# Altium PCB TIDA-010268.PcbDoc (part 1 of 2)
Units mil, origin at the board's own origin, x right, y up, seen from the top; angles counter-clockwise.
Board outline 3937.2 x 2362.29 mil, 2 copper layers (Top Layer, Bottom Layer), stack 62 mil thick; 154 components, 100 nets, 480 pads, 602 vias.
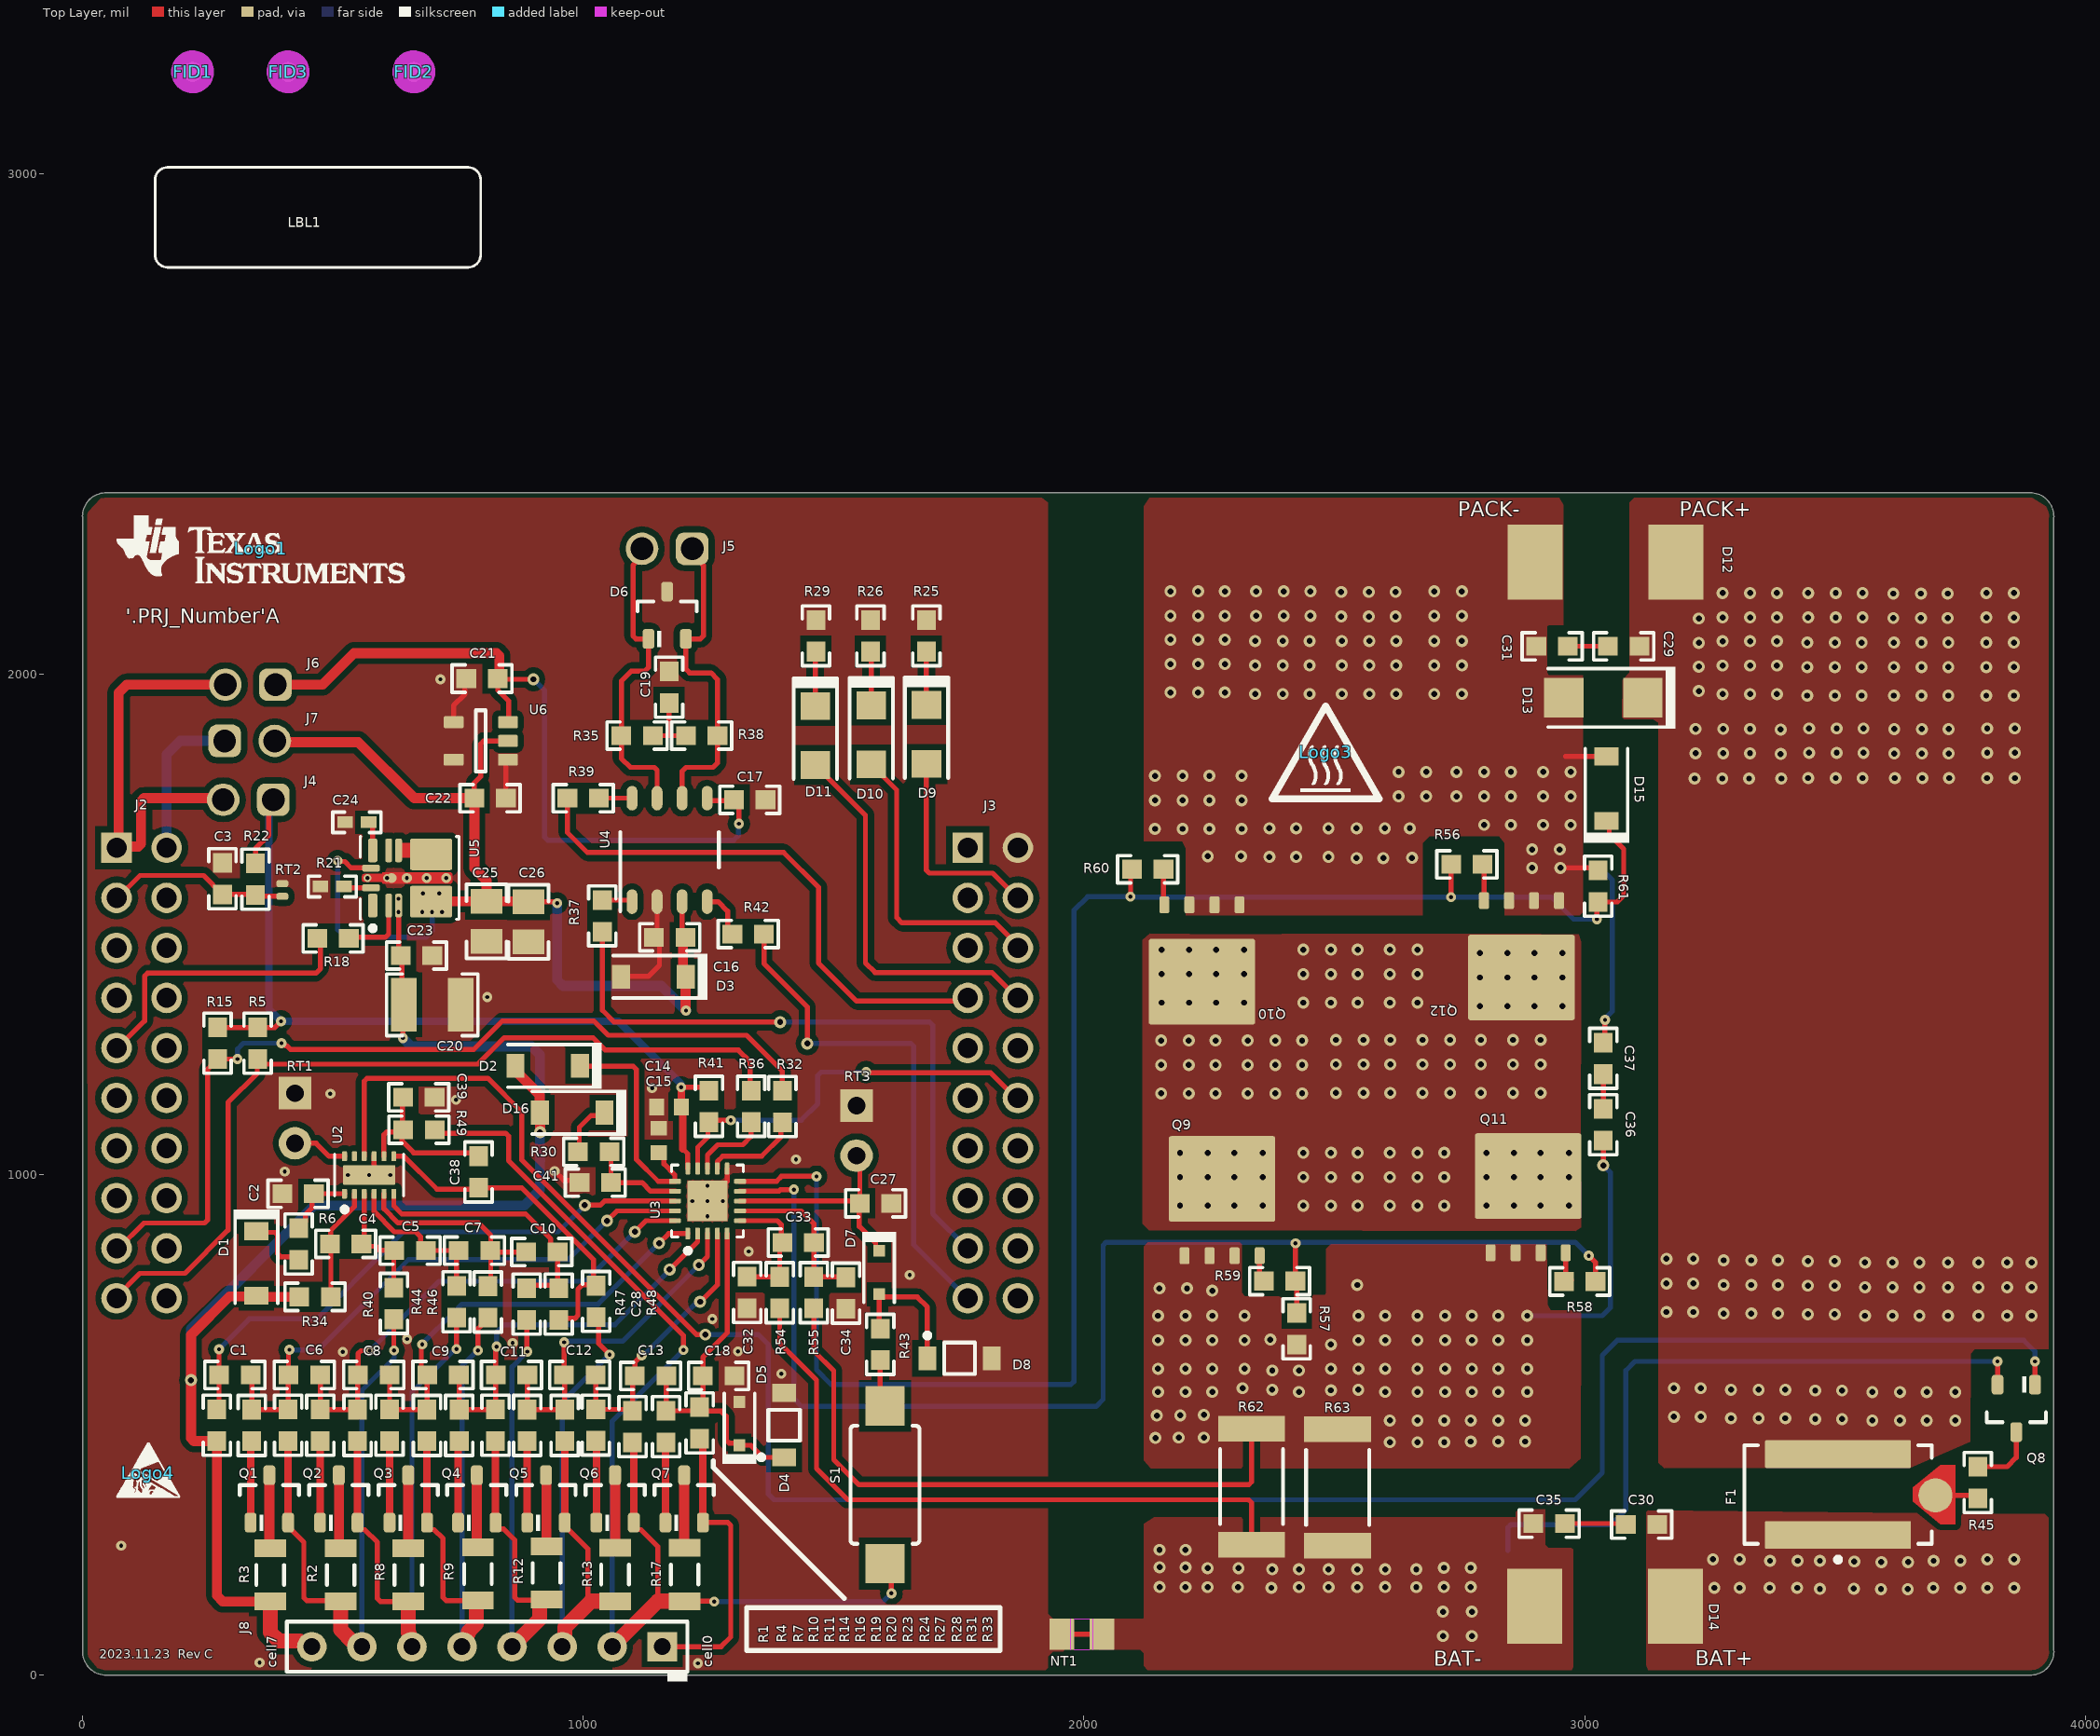
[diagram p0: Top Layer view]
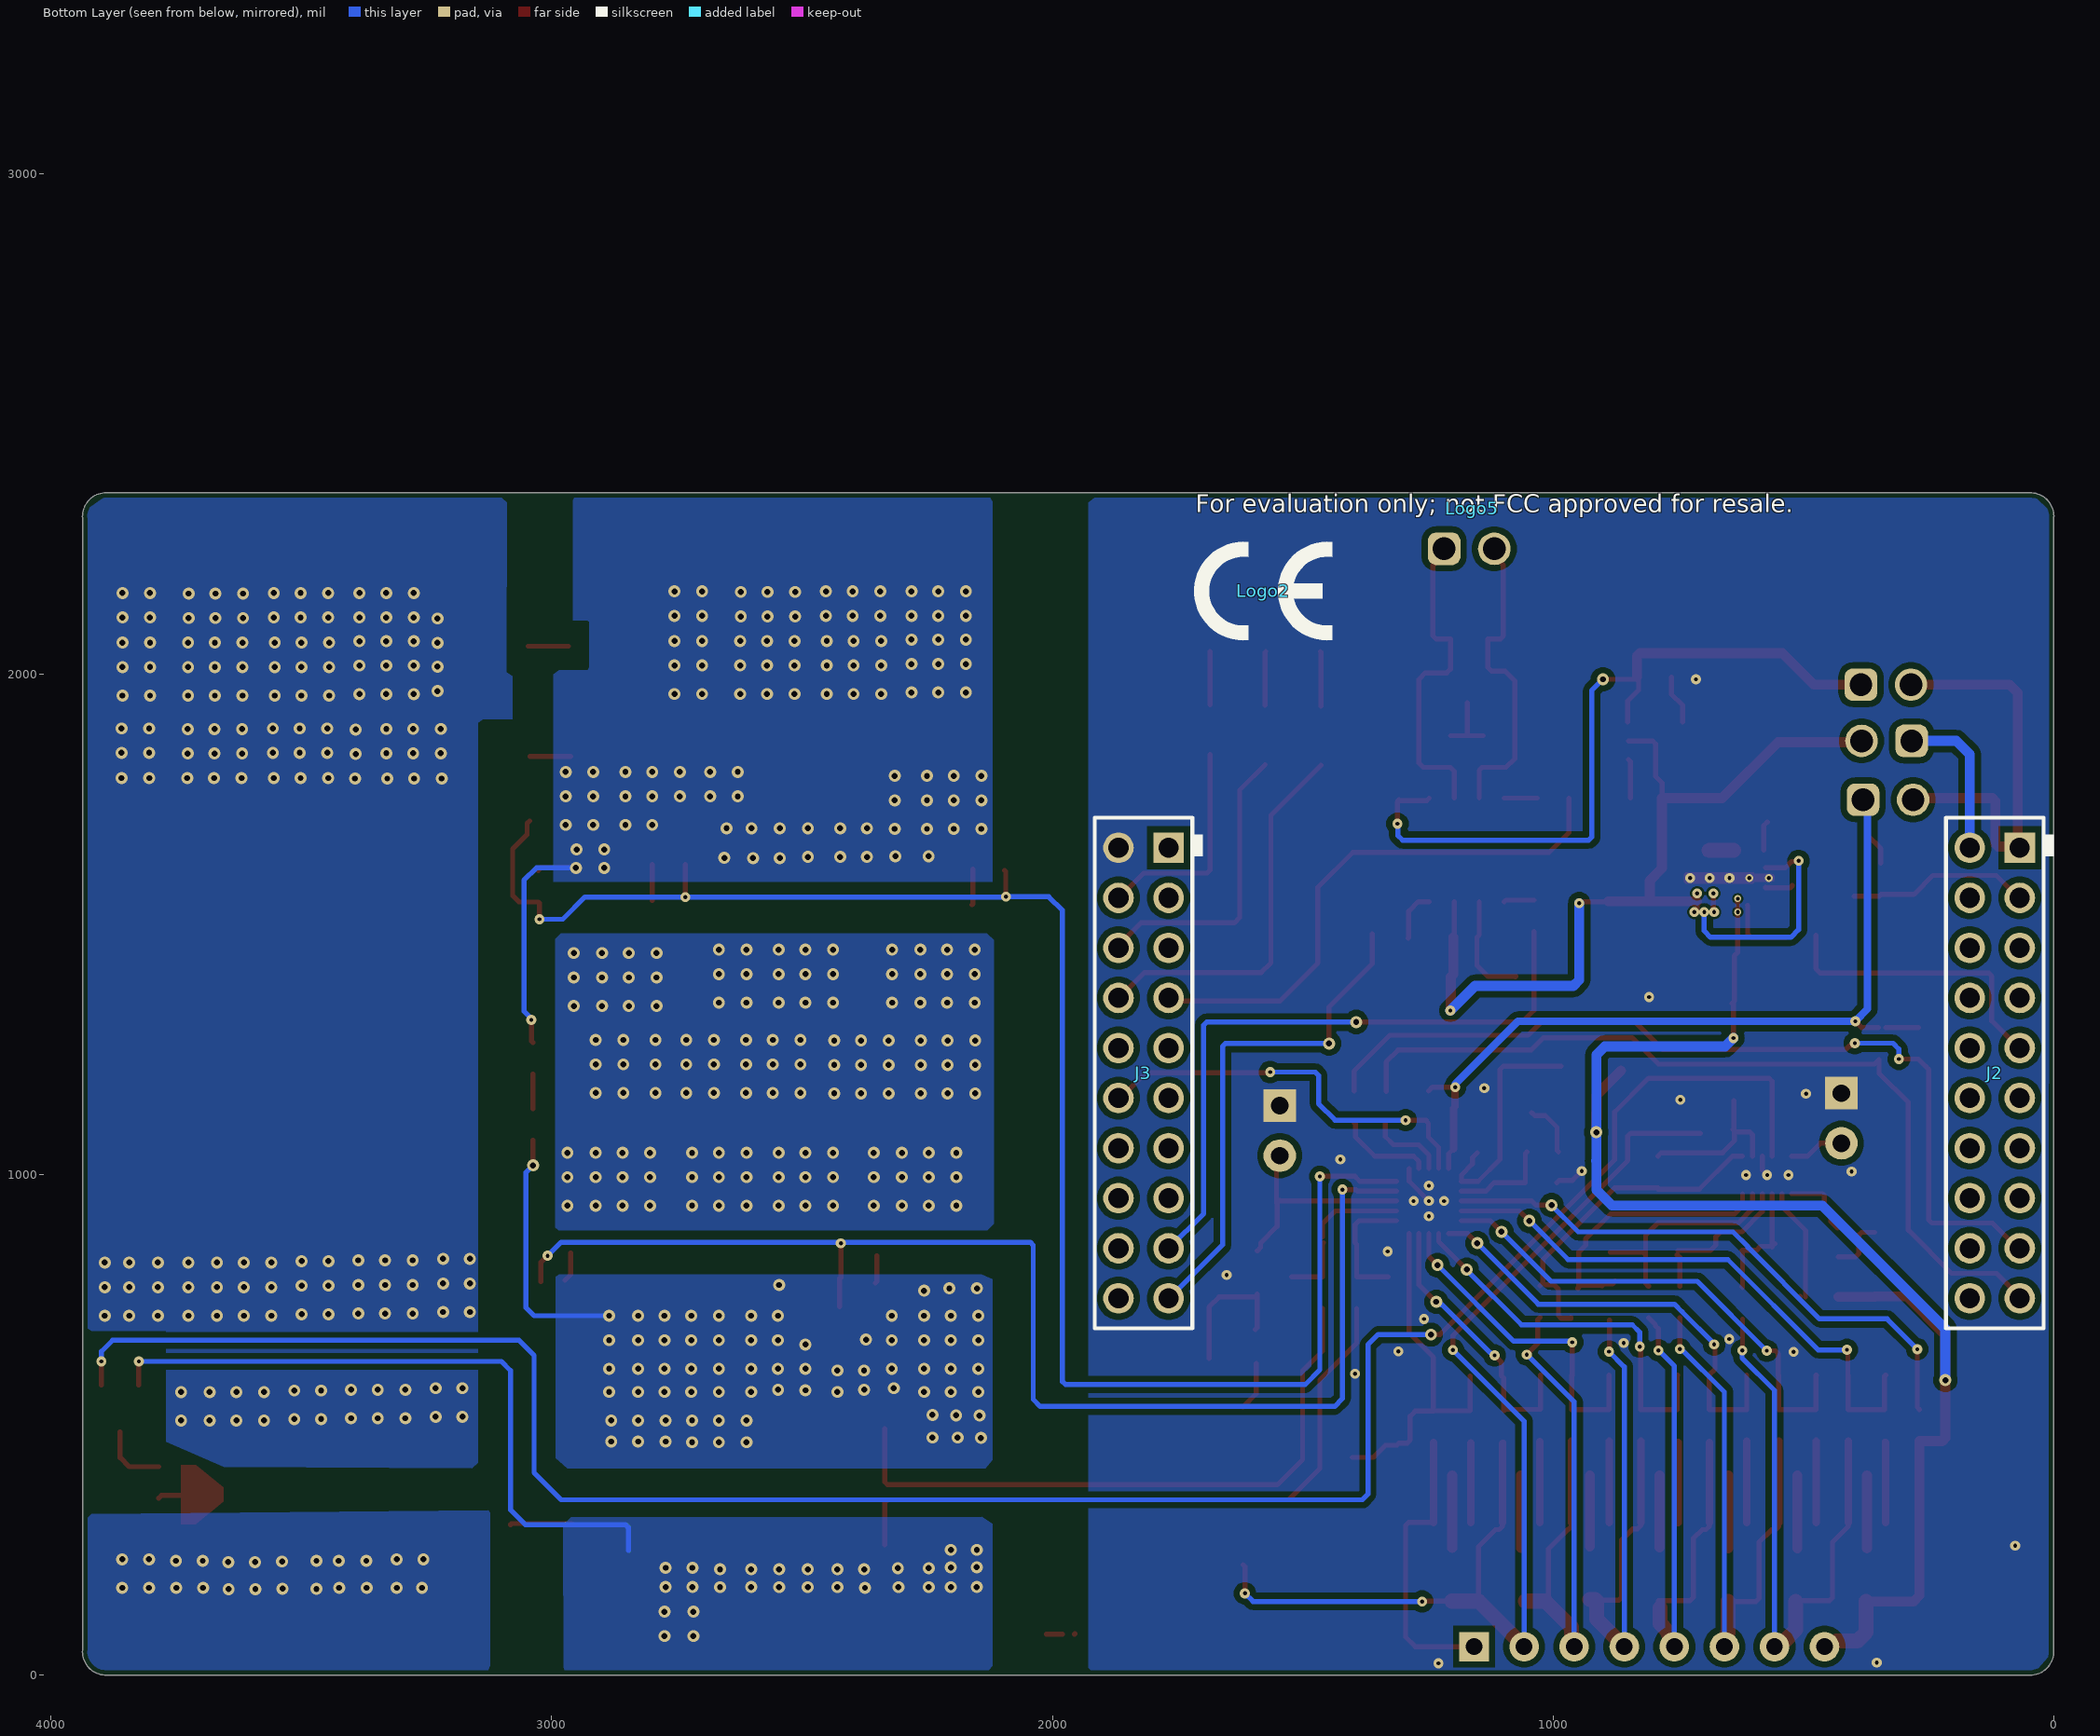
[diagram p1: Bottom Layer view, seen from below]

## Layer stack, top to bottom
Top Solder: solder mask 0.4, Solder Resist, Dk 3.5
Top Layer: signal copper 1.4
Dielectric1: core 59.2, FR-4 High Tg, Dk 4.8
Bottom Layer: signal copper 1.4
Bottom Solder: solder mask 0.4, Solder Resist, Dk 3.5

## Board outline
47.27,0.06 cw(c47.48,47.45) 0.09,47.99 0,2314.52 -0.09,2315.12 cw(c47.3,2314.91) 47.84,2362.29 47.69,2362.2 3887.56,2362.2 3889.92,2362.29 cw(c3889.71,2314.91) 3937.09,2314.37 3937.01,2312.76 3937.01,49.03 3937.11,47.19 cw(c3889.73,47.39) 3889.19,0.01 3887.97,0

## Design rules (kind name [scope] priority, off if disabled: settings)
AcuteAngle [InNet('5V')] p1: minimum=1.00000000000000E+0001 checktracksonly=FALSE
AcuteAngle AcuteAngle_ALL [All] p2: minimum=4.50000000000000E+0001 checktracksonly=FALSE
AssemblyTestPointUsage [All] p1: valid=2
BoardOutlineClearance BoardOutlineClearance_MountingHoles [OnCopper and InComponentClass('Mounting Holes')] p1: gap=10 ignorepadtopadclearanceinfootprint=FALSE
BoardOutlineClearance BoardOutlineClearance_Poly [OnCopper and IsPoly] p2: gap=10 ignorepadtopadclearanceinfootprint=FALSE
BoardOutlineClearance [OnCopper and Not InComponentClass('Logo') and not InComponentClass('FiducialMark') and not InRegion(1000,500,4000,800) and not InPoly] p3: gap=10 ignorepadtopadclearanceinfootprint=FALSE
Clearance [Not  (InNamedPolygon('Top Layer-GND')) vs InComponent('U5')] p1: gap=4 ignorepadtopadclearanceinfootprint=TRUE
Clearance Clearance_Keepouts [((IsTrack Or IsArc) And Not InPoly) And IsFree and IsKeepOut vs ((IsTrack Or IsArc) And Not InPoly) And IsFree and IsKeepOut] p2: gap=0 ignorepadtopadclearanceinfootprint=FALSE
Clearance Clearance_Poly [InPolygon] p3: gap=12 ignorepadtopadclearanceinfootprint=TRUE
Clearance Clearance_FiducialMark [IsKeepOut and InComponentClass('FiducialMark') vs IsPad and InComponentClass('FiducialMark')] p4: gap=0 ignorepadtopadclearanceinfootprint=FALSE
Clearance Clearance_All [All] p5: gap=7.87 ignorepadtopadclearanceinfootprint=TRUE
ComponentClearance ComponentClearance_MountingHoles_FiducialMarks [InComponentClass('Mounting Holes') vs InComponentClass('FiducialMark')] p1: gap=50 collisioncheckmode=3 verticalgap=10 showdistances=FALSE
ComponentClearance ComponentClearance_Shunt [InComponentClass('Header') vs InComponentClass('Shunt')] p2: gap=0 collisioncheckmode=3 verticalgap=0 showdistances=FALSE
ComponentClearance ComponentClearance_Logo [InComponentClass('Logo')] p3: gap=30 collisioncheckmode=3 verticalgap=10 showdistances=FALSE
ComponentClearance ComponentClearance_ScrewToNut [(HasFootprint('NY PMS 440 0025 PH')) vs (HasFootprint('Keystone_1902C'))] p4: gap=5 collisioncheckmode=3 verticalgap=10 showdistances=FALSE
ComponentClearance ComponentClearance_MountingHoles [InComponentClass('Mounting Holes')] p5: gap=100 collisioncheckmode=3 verticalgap=100000 showdistances=FALSE
ComponentClearance ComponentClearance_SmallPassives [HasFootprint('0201*') or HasFootprint('0402*') or HasFootprint('0508') or HasFootprint('0603*') or HasFootprint('0612') or HasFootprint('0805*') or HasFootprint('0815*') or HasFootprint('0830*') or HasFootprint('1206*') or HasFootprint('1210*') or HasFootprint('1808*') or HasFootprint('1812*') or HasFootprint('1825*') or HasFootprint('2010*') or HasFootprint('2220*') or HasFootprint('2225*') or HasFootprint('2512*') or HasFootprint('2728*') or HasFootprint('3518*') vs HasFootprint('0201*') or HasFootprint('0402*') or HasFootprint('0508') or HasFootprint('0603*') or HasFootprint('0612') or HasFootprint('0805*') or HasFootprint('0815*') or HasFootprint('0830*') or HasFootprint('1206*') or HasFootprint('1210*') or HasFootprint('1808*') or HasFootprint('1812*') or HasFootprint('1825*') or HasFootprint('2010*') or HasFootprint('2220*') or HasFootprint('2225*') or HasFootprint('2512*') or HasFootprint('2728*') or HasFootprint('3518*')] p6: gap=14.96 collisioncheckmode=3 verticalgap=10 showdistances=FALSE
ComponentClearance ComponentClearance_THtoSMT [IsThruComponent vs IsSMTComponent] p7: gap=25 collisioncheckmode=3 verticalgap=25 showdistances=FALSE
ComponentClearance ComponentClearance_THtoTH [IsThruComponent vs IsThruComponent] p8: gap=10 collisioncheckmode=3 verticalgap=30 showdistances=FALSE
ComponentClearance [All] p9: gap=10 collisioncheckmode=3 verticalgap=10 showdistances=FALSE
DiffPairsRouting [All] p1: maxlimit=100 minlimit=10 mostfreqgap=10 toplayer_minwidth=15 toplayer_maxwidth=15 toplayer_prefwidth=15 bottomlayer_minwidth=15 bottomlayer_maxwidth=15 bottomlayer_prefwidth=15 maxuncoupledlength=1000
FabricationTestPointUsage TestPointUsage [All] p1: valid=2 allowmultiple=FALSE
FabricationTestpoint Testpoint [All] p1: side=3 testpointundercomponent=TRUE minsize=40 maxsize=100 preferedsize=60 minholesize=0 maxholesize=40 preferedholesize=32 testpointgrid=1 allowsidetop=TRUE allowsidebottom=TRUE usegrid=TRUE gridtolerance=0.01
FanoutControl Fanout_LCC [IsLCC] p1: bgadir=Out bgaviamode=Centered fanoutstyle=Auto fanoutdirection=Alternating viagrid=1 // Fanout_LCC (Default Rule)
FanoutControl Fanout_BGA [IsBGA] p2: bgadir=Out bgaviamode=Centered fanoutstyle=Auto fanoutdirection=Alternating viagrid=1 // Fanout_BGA (Default Rule)
FanoutControl Fanout_Default [All] p4: bgadir=Out bgaviamode=Centered fanoutstyle=Auto fanoutdirection=Alternating viagrid=1 // Fanout_Default (Default Rule)
FanoutControl Fanout_Small [(CompPinCount < 5)] p5: bgadir=Out bgaviamode=Centered fanoutstyle=Auto fanoutdirection=OutThenIn viagrid=1 // Fanout_Small (Default Rule)
HoleSize [All] p1: absolutevalues=TRUE maxlimit=251 minlimit=7.87 maxpercent=80.000 minpercent=20.000
MinimumAnnularRing MinimumAnnularRing_ThermalPadVias [IsVia and InAnyComponent] p1: minimumring=2
MinimumAnnularRing [All] p2: minimumring=2
MinimumSolderMaskSliver MinimumSolderMaskSliver_Logo [InComponentClass('Logo') vs InComponentClass('Logo')] p1: minsoldermaskwidth=0.7
MinimumSolderMaskSliver [All] p2: minsoldermaskwidth=3.94
PlaneConnect [All] p1: planeconnectstyle=Relief reliefexpansion=10 reliefentries=4 reliefconductorwidth=10 reliefairgap=10
PolygonConnect [All] p1: connectstyle=Direct reliefconductorwidth=10 reliefentries=4 polygonreliefangle="90 Angle" airgapwidth=10
RoutingVias ThermalPadVias [IsVia and InAnyComponent] p1: holewidth=5 width=19.68 viastyle="Through Hole" minholewidth=5 minwidth=10 maxholewidth=12.99 maxwidth=25
RoutingVias [All] p2: holewidth=16 width=34 viastyle="Through Hole" minholewidth=5 minwidth=18 maxholewidth=40 maxwidth=65
SilkToBoardRegionClearance [Not ((IsComment or IsDesignator) And (Hide <> 'False')) and not InRegion(1000,500,4000,800)] p1:
SilkToSilkClearance SilkToSilkClearance_Pb-FreeLogo [(HasFootprint('Pb-Free_Overlay_Medium') OR HasFootprint('Pb-Free_Overlay_Small')) vs (HasFootprint('Pb-Free_Overlay_Medium') OR HasFootprint('Pb-Free_Overlay_Small'))] p1: silktosilkclearance=0
SilkToSilkClearance [All] p2: silktosilkclearance=3.94
SilkToSolderMaskClearance SilkToComponentPadClearance [(IsPad or IsFill or IsRegion) and InAnycomponent] p1: minsilkscreentomaskgap=3 clearancetoexposedcopper=TRUE
SilkToSolderMaskClearance "Silk to Solder Mask Opening" [All] p2: minsilkscreentomaskgap=3.94 clearancetoexposedcopper=FALSE
SolderMaskExpansion [All] p1: expansion=1.97 istentingtop=FALSE
UnRoutedNet [All] p1: checkbadconnections=TRUE
Width [InNet('5V')] p1: maxlimit=50 minlimit=1 preferedwidth=1
Width Width_all [All] p2: maxlimit=100 minlimit=6 preferedwidth=10 checkconnectedcopper=TRUE
14 further rules are at their usual default settings.

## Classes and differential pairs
component class "TIDA-010268_Power Rail": C29 C30 C31 C32 C33 C34 C35 C36 C37 D12 D13 D14 D15 F1 NT1 Q8 Q9 Q10 Q11 Q12 R45 R54 R55 R56 R57 R58 R59 R60 R61 R62 R63
component class "TIDA-010268_Monitor and CB": C1 C2 C3 C4 C5 C6 C7 C8 C9 C10 C11 C12 C13 C14 C15 C16 C17 C18 C19 C20 C21 C22 C23 C24 C25 C26 C27 C28 C38 C39 C41 D1 D2 D3 D4 D5 D6 D7 D8 D9 D10 D11 D16 J2 J3 J4 J5 J6 J7 J8 Q1 Q2 Q3 Q4 Q5 Q6 Q7 R1 R2 R3 R4 R5 R6 R7 R8 R9 R10 R11 R12 R13 R14 R15 R16 R17 R18 R19 R20 R21 R22 R23 R24 R25 R26 R27 R28 R29 R30 R31 R32 R33 R34 R35 R36 R37 R38 R39 R40 R41 R42 R43 R44 R46 R47 R48 R49 RT1 RT2 RT3 S1 U2 U3 U4 U5 U6
component class Header: J4 J5 J6 J7 J8
component class Logo: Logo1
component class TIDA-010268_Hardware: FID1 FID2 FID3 LBL1 Logo1 Logo2 Logo3 Logo4 Logo5
component class FiducialMark: FID1 FID2 FID3
component class Label: LBL1

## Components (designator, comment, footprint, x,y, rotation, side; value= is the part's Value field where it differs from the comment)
C1 "GRM188R71H224KAC4D" 0603 304.27,599.57 r0 top value=0.22uF
C2 "GRM188R72A104KA35J" 0603 430.47,961.86 r0 top value=0.1uF
C3 "GRM188R71H471KA01D" 0603 279.6,1591.23 r90 top value=470pF
C4 "GRM188R72A104KA35J" 0603 525.65,861.74 r0 top value=0.1uF
C5 "GRM188R72A104KA35J" 0603 654.43,848.32 r0 top value=0.1uF
C6 "GRM188R71H224KAC4D" 0603 442.95,599.57 r0 top value=0.22uF
C7 "GRM188R72A104KA35J" 0603 782.67,848.32 r0 top value=0.1uF
C8 "GRM188R71H224KAC4D" 0603 581.74,599.57 r0 top value=0.22uF
C9 "GRM188R71H224KAC4D" 0603 720.04,599.57 r0 top value=0.22uF
C10 "GRM188R72A104KA35J" 0603 917.24,845.41 r0 top value=0.1uF
C11 "GRM188R71H224KAC4D" 0603 856.78,599.57 r0 top value=0.22uF
C12 "GRM188R71H224KAC4D" 0603 993.23,599.57 r0 top value=0.22uF
C13 "GRM188R71H224KAC4D" 0603 1134.68,597.75 r0 top value=0.22uF
C14 "GRM188R61E105KA12D" CAPC1608X90X35LL10T15 1171.52,1135.5 r0 top value=1uF
C15 "GRM188R61E105KA12D" CAPC1608X90X35LL10T15 1150.82,1068.27 r90 top value=1uF
C16 "GRM188R72A104KA35J" 0603 1172.86,1474.25 r0 top value=0.1uF
C17 "GRM188R72A104KA35J" 0603 1332.54,1748.9 r180 top value=0.1uF
C18 "GRM188R71H224KAC4D" 0603 1270.57,597.75 r0 top value=0.22uF
C19 "GRM188R72A104KA35J" 0603 1171.52,1973.78 r90 top value=0.1uF
C20 "GRM32CR72A105KA35L" 1210_180 698.45,1339.32 r0 top value=1uF
C21 "GRM188C71E225KE11D" 0603 797.88,1990.96 r180 top value=2.2uF
C22 "GRM188C71E225KE11D" 0603 814.05,1752.08 r0 top value=2.2uF
C23 "GRM188R72A104KA35J" 0603 667.11,1437.56 r0 top value=0.1uF
C24 "GRM155R6YA105KE11D" 0402 548,1704 r180 top value=1uF
C25 "GRM21BC81C226ME44L" 0805_HV 807.06,1506.08 r270 top value=22uF
C26 "GRM21BC81C226ME44L" 0805_HV 890.87,1505.07 r270 top value=22uF
C27 "GRM188R71H471KA01D" 0603 1583.89,942.47 r0 top value=470pF
C28 "GRM188R72A104KA35J" 0603 950.88,741.26 r270 top value=0.1uF
C29 "GRM188R72A104KA35J" 0603 3078,2055.52 r180 top value=0.1uF
C30 "GRM188R72A104KA35J" 0603 3113.74,300.87 r180 top value=0.1uF
C31 "GRM188R72A104KA35J" 0603 2935.05,2055.52 r180 top value=0.1uF
C32 "GRM188R72A104KA35J" 0603 1327.44,764.67 r90 top value=0.1uF
C33 "GRM188R72A104KA35J" 0603 1429.42,864.29 r0 top value=0.1uF
C34 "GRM188R72A104KA35J" 0603 1524.69,763.37 r270 top value=0.1uF
C35 "GRM188R72A104KA35J" 0603 2929,303 r180 top value=0.1uF
C36 "GRM188R72A104KA35J" 0603 3037.34,1099.87 r90 top value=0.1uF
C37 "GRM188R72A104KA35J" 0603 3037.34,1232.19 r90 top value=0.1uF
C38 "GRM188R72A104KA35J" 0603 790.97,1005.3 r90 top value=0.1uF
C39 "GRM188R72A104KA35J" 0603 671.59,1154.42 r0 top value=0.1uF
C41 "GRM188R72A104KA35J" 0603 1024.06,983.98 r0 top value=0.1uF
D1 "1N6263W-7-F" SOD-123 347.23,822.68 r270 top value=60V
D2 "1N6263W-7-F" SOD-123 929.06,1217.36 r180 top value=60V
D3 "MMSZ4690T1G" SOD-123 1140.11,1395.22 r180 top value=5.6V
D4 "MMSZ4685T1G" ONSC-SOD-123-2-425-04_V 1401.18,499.63 r90 top
D5 "BAT42WS-7-F" SOD-323 1312.15,502.79 r90 top value=30V
D6 "NUP2105L" SOT-23 1167.67,2117.55 r90 top value=24V
D7 "PMEG1030EJ,115" SOD-323F 1591.04,804.48 r270 top value=10V
D8 "MMSZ4678T1G" ONSC-SOD-123-2-425-04_V 1751.59,633.07 r0 top
D9 "150120RS75000" WL_SMCW_RED_1206 1685.38,1879.29 r270 top value=Red
D10 "150120RS75000" WL_SMCW_RED_1206 1575.11,1878.36 r270 top value=Red
D11 "150120RS75000" WL_SMCW_RED_1206 1463.38,1877.29 r270 top value=Red
D12 "SMCJ30CA" SMC_Bi 3041.87,2223.52 r0 top value=30V
D13 "MURA110T3G" SMA 3037.34,1952.56 r180 top value=100V
D14 "SMCJ30CA" SMC_Bi 3041,138 r0 top value=30V
D15 "MMSZ5246B-7-F" SOD-123 3043.55,1771.02 r90 top value=16V
D16 "1N6263W-7-F" SOD-123 978.07,1123.72 r180 top value=60V
F1 "SFK-3045" "FP-SFK-3045_FUSE, SMT-MFG" 3506,361 r180 top
FID1 "Fiducial" Fiducial10-20 220.02,3203.15 r0 top
FID2 "Fiducial" Fiducial10-20 661.63,3203.15 r0 top
FID3 "Fiducial" Fiducial10-20 410.62,3203.15 r0 top
J2 "SSQ-110-03-T-D" Samtec_SSQ-110-03-x-D 118,1203 r270 bottom
J3 "SSQ-110-03-T-D" Samtec_SSQ-110-03-x-D 1818,1203 r270 bottom
J4 "61300211121" WURTH_61300211121 331.01,1748.9 r180 top
J5 "61300211121" WURTH_61300211121 1167.58,2250.31 r180 top
J6 "61300211121" WURTH_61300211121 335.26,1978.81 r180 top
J7 "61300211121" WURTH_61300211121 334.01,1866.5 r0 top
J8 "800-10-008-10-001000" Mill-Max_800-10-008-10-001000 807.97,57.03 r180 top
LBL1 "THT-14-423-10" Label_650x200 470.01,2912.4 r0 top
Logo1 "Texas Instruments" TI_Stacked_Overlay_Small_Vertical 355.76,2250.31 r270 top
Logo2 "CE Mark" CE_Mark_5mm 1578.95,2165.68 r180 bottom
Logo3 "CAUTION HOT SURFACE" IEC_HotSurface_small 2482.48,1843.7 r0 top (schematic designator LOGO3)
Logo4 "ESD Susceptible" ESD_Overlay_Small 130.47,403.8 r0 top
Logo5 "FCC disclaimer" FCC_disclaimer 1161.67,2331 r180 bottom
NT1 "Net-Tie" Net-Tie_0805_HV_NoOverlay 1996.02,81.92 r0 top net-tie
Q1 "BSR14" SOT-23 373.16,352.25 r90 top value="40 V"
Q2 "BSR14" SOT-23 511.85,352.25 r90 top value="40 V"
Q3 "BSR14" SOT-23 650.64,352.25 r90 top value="40 V"
Q4 "BSR14" SOT-23 787.52,352.25 r90 top value="40 V"
Q5 "BSR14" SOT-23 925.68,352.25 r90 top value="40 V"
Q6 "BSR14" SOT-23 1063.68,352.25 r90 top value="40 V"
Q7 "BSR14" SOT-23 1201.68,352.25 r90 top value="40 V"
Q8 "IRLML2060TRPBF" SOT-23 3862,533 r270 top value=60V
Q9 "CSD18540Q5B" DNK0008A 2275.82,949 r90 top value=60V
Q10 "CSD18540Q5B" DNK0008A 2235.64,1427.95 r270 top value=60V
Q11 "CSD18540Q5B" DNK0008A 2887.13,954.69 r90 top value=60V
Q12 "CSD18540Q5B" DNK0008A 2873.8,1436.38 r270 top value=60V
R1 "CRCW0603100RFKEA" 0603 268.31,499.25 r90 top value=100
R2 "CRCW120680R6FKEA" RESC3216X60X45LL10T20 515.68,200.45 r90 top
R3 "CRCW120680R6FKEA" RESC3216X60X45LL10T20 374.87,200.45 r90 top
R4 "CRCW0603300RJNEA" 0603 337.97,499.02 r90 top value=300
R5 "CRCW060310K0FKEA" 0603 349.86,1262.56 r90 top value=10.0k
R6 "CRCW0603300RJNEA" 0603 431.84,861.55 r90 top value=300
R7 "CRCW0603100RFKEA" 0603 410.57,499.25 r90 top value=100
R8 "CRCW120680R6FKEA" RESC3216X60X45LL10T20 650.64,200.45 r90 top
R9 "CRCW120680R6FKEA" RESC3216X60X45LL10T20 789.6,202.36 r90 top
R10 "CRCW0603300RJNEA" 0603 474.86,499.25 r90 top value=300
R11 "CRCW0603100RFKEA" 0603 549.25,499.02 r90 top value=100
R12 "CRCW120680R6FKEA" RESC3216X60X45LL10T20 926.72,204.28 r90 top
R13 "CRCW120680R6FKEA" RESC3216X60X45LL10T20 1063.68,201.13 r90 top
R14 "CRCW0603300RJNEA" 0603 613.24,499.25 r90 top value=300
R15 "CRCW060310K0FKEA" 0603 269.82,1262.56 r90 top value=10.0k
R16 "CRCW0603100RFKEA" 0603 688.04,499.02 r90 top value=100
R17 "CRCW120680R6FKEA" RESC3216X60X45LL10T20 1202.57,201.13 r90 top
R18 "CRCW06031K00FKEA" 0603 500.51,1471.78 r0 top value=1.00k
R19 "CRCW0603300RJNEA" 0603 752.46,499.02 r90 top value=300
R20 "CRCW0603100RFKEA" 0603 824.92,499.25 r90 top value=100
R21 "CRCW040241K2FKED" 0402 498.79,1575.6 r0 top value=41.2k
R22 "CRCW060310K0FKEA" 0603 345.55,1590.37 r90 top value=10.0k
R23 "CRCW0603300RJNEA" 0603 888.28,499.02 r90 top value=300
R24 "CRCW0603100RFKEA" 0603 963.08,499.02 r90 top value=100
R25 "CRCW0603470RJNEA" 0603 1685.38,2076.29 r270 top value=470
R26 "CRCW0603470RJNEA" 0603 1573.77,2076.29 r270 top value=470
R27 "CRCW0603300RJNEA" 0603 1025.15,499.63 r90 top value=300
R28 "CRCW0603100RFKEA" 0603 1098.57,496.74 r90 top value=100
R29 "CRCW0603470RJNEA" 0603 1464.88,2076.29 r270 top value=470
R30 "CRCW0603300RJNEA" 0603 1020.85,1045.5 r0 top value=300
R31 "CRCW0603300RJNEA" 0603 1165.62,496.74 r90 top value=300
R32 "CRCW0603100RJNEA" 0603 1397.69,1135.9 r90 top value=100
R33 "CRCW0603100RFKEA" 0603 1232.59,504.17 r90 top value=100
R34 "CRCW06031K00FKEA" 0603 464.47,755.77 r0 top value=1.00k
R35 "CRCW060360R4FKEA" 0603 1107.69,1877.02 r180 top value=60.4
R36 "CRCW0603100RJNEA" 0603 1335.46,1136.36 r90 top value=100
R37 "CRCW0603100RJNEA" 0603 1038.18,1516.88 r90 top value=100
R38 "CRCW060360R4FKEA" 0603 1236.51,1877.02 r180 top value=60.4
R39 "CRCW0603100RJNEA" 0603 1000.05,1752.08 r0 top value=100
R40 "CRCW06031K00FKEA" 0603 621.79,742.68 r90 top value=1.00k
R41 "CRCW060310K0FKEA" 0603 1251.25,1136.36 r270 top value=10.0k
R42 "CRCW0603100RJNEA" 0603 1329.41,1480.78 r180 top value=100
R43 "CRCW060310K0FKEA" 0603 1593.1,660.87 r90 top value=10.0k
R44 "CRCW06031K00FKEA" 0603 747.13,745.88 r90 top value=1.00k
R45 "CRCW0603300RJNEA" 0603 3785,385 r270 top value=300
R46 "CRCW06031K00FKEA" 0603 809.5,745.63 r90 top value=1.00k
R47 "CRCW06031K00FKEA" 0603 887.25,741.26 r90 top value=1.00k
R48 "CRCW06031K00FKEA" 0603 1025.83,746.78 r90 top value=1.00k
R49 "CRCW06031K00FKEA" 0603 672.11,1089.83 r180 top value=1.00k
R54 "CRCW0603100RFKEA" 0603 1392.46,764.3 r90 top value=100
R55 "CRCW0603100RFKEA" 0603 1460.46,764.3 r270 top value=100
R56 "CRCW0603330RJNEA" 0603 2764.76,1619.77 r180 top value=330
R57 "CRCW060310M0JNEA" 0603 2424.99,692.09 r90 top value=10Meg
R58 "CRCW0603330RJNEA" 0603 2990.25,786.51 r0 top value=330
R59 "CRCW0603330RJNEA" 0603 2390.88,787.39 r0 top value=330
R60 "CRCW0603330RJNEA" 0603 2127.23,1610.22 r180 top value=330
R61 "CRCW060310M0JNEA" 0603 3026.82,1576.22 r270 top value=10Meg
R62 "CSNL2512FT2L00" 2512 2334.73,376.73 r90 top value=0.002
R63 "CSNL2512FT2L00" 2512 2506.54,375.14 r90 top value=0.002
RT1 "103AT-2" THERMISTOR_103AT-2 424.25,1112.67 r270 top value=10k
RT2 "TMP6131DECR" DEC0002A 399.19,1568.71 r270 top
RT3 "103AT-2" THERMISTOR_103AT-2 1545.86,1087.95 r270 top value=10k
S1 "RS-032G05A3-SM RT" SW_RS-032G05A3-SM 1602.59,380.47 r270 top
U2 "BQ7720700DSSR" DSS0012B-MFG 572.51,999.26 r90 top
U3 "BQ76907RGR" RGR0020A-MFG 1248.18,947.26 r90 top
U4 "TCAN1042HGVDQ1" D0008A_L 1172.54,1648.74 r90 top
U5 "TPSM365R6V5RDNR" RDN0011A-MFG 656.82,1592.63 r90 top
U6 "TLV70433DBVT" DBV0005A_N 795.35,1866.5 r180 top

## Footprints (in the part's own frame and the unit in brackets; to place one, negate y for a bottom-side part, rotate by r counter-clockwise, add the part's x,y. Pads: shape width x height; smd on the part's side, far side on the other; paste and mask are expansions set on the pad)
0402 [mm] "0402 from SM-752 data"
  rect 0.8x0.6 smd: 1(-0.6,0) 2(0.6,0)
  silkscreen extent -1.22,-0.52 1.22,0.52, body extent -0.55,-0.3 0.55,0.3, height 0.6
0603 [mm] "0603 from SM-752 data"
  rect 1x0.95 smd: 1(-0.8,0) 2(0.8,0)
  silkscreen extent -1.52,-0.69 1.52,0.69, body extent -0.87,-0.47 0.87,0.47, height 1
0805_HV [mil] "0805 with 30mil clearance between pads"
  rect 50x63 smd: 1(-40,0) 2(40,0)
  silkscreen extent -74,-40 74,40, body extent -43,-29 43,29, height 57
1210_180 [mm] "1210"
  rect 1.3x2.7 smd: 1(-1.45,0) 2(1.45,0)
  silkscreen extent -2.32,-1.57 2.32,1.57, body extent -1.7,-1.35 1.7,1.35, height 1.8
2512 [mm] "Chip Resistor, Body 6.3x3.2mm, IPC Medium Density"
  rect 1.3x3.4 smd: 1(-2.95,0) 2(2.95,0)
  silkscreen extent -1.9,-1.6 1.9,1.6, body extent -3.22,-1.67 3.22,1.67, height 0.71
CAPC1608X90X35LL10T15 [mm] "Chip Capacitor, 2-Leads, Body 1.60x0.80mm, IPC High Density"
  rect 0.75x0.85 smd: 1(-0.625,0) 2(0.625,0)
  body extent -0.85,-0.45 0.85,0.45, height 0.9
CE_Mark_5mm [mil] "Minimum text height for CE Mark"
  silkscreen extent -138,-98 138,98
D0008A_L [mm] "SOIC, 8-Leads, Body 4.9x3.9mm, Pitch 1.27mm, IPC High Density"
  oval 1.25x0.55 smd: 1(-2.625,1.905) 2(-2.625,0.635) 3(-2.625,-0.635) 4(-2.625,-1.905) 5(2.625,-1.905) 6(2.625,-0.635) 7(2.625,0.635) 8(2.625,1.905)
  silkscreen extent -3.1,-2.5 0.9,2.5, body extent -3,-2.45 3,2.45, height 1.63
DBV0005A_N [mm] "SOT23, 5-Leads, Body 2.9x1.6mm, Pitch 0.95mm, Lead Span 2.8mm, IPC Medium Density"
  rrect17% 1x0.6 smd: 1(-1.375,0.95) 2(-1.375,0) 3(-1.375,-0.95) 4(1.375,-0.95) 5(1.375,0.95)
  silkscreen extent -0.25,-1.55 0.25,1.55, body extent -1.42,-1.46 1.42,1.46, height 1.09
DEC0002A [mm] "X1SON-2"
  rrect57% 0.35x0.6 smd paste-0.5 mask-0.05: 1(-0.325,0) 2(0.325,0)
  rrect33% 0.3x0.5 on Top Paste: 1S(-0.35,0) 2S(0.35,0)
  body extent -0.5,-0.3 0.5,0.3, height 0.5
DNK0008A [mm] "SON, 8-Leads, Body 5x6mm"
  rrect39% 0.86x0.51 smd paste-0.05 mask-0.05: 1(-2.82,1.905) 2(-2.82,0.635) 3(-2.82,-0.635) 4(-2.82,-1.905) 5(2.82,-1.905) 6(2.82,-0.635) 7(2.82,0.635) 8(2.82,1.905)
  rrect40% 0.25x0.555 on Top Solder: 9(-0.83,2.372) 9(-0.83,-2.372)
  rrect40% 0.25x0.555 on Top Paste: 9(-0.83,2.372) 9(-0.83,-2.372)
  rrect11% 0.95x1.13 on Top Paste: 9(-0.535,1.33) 9(-0.535,0) 9(-0.535,-1.33) 9(0.615,1.33) 9(0.615,0) 9(0.615,-1.33) 9(1.765,-1.33) 9(1.765,0) 9(1.765,1.33)
  rrect3% 3.58x4 on Top Solder: 9(0.75,0)
  rrect5% 4.34x5.4 smd paste-3 mask-3: 9(1.08,0)
  body extent -3.05,-2.55 3.05,2.55, height 1.06
DSS0012B-MFG [mm]
  rrect40% 0.5x0.25 smd paste+0 mask+0: 1(-0.95,1.25) 2(-0.95,0.75) 3(-0.95,0.25) 4(-0.95,-0.25) 5(-0.95,-0.75) 6(-0.95,-1.25) 7(0.95,-1.25) 8(0.95,-0.75) 9(0.95,-0.25) 10(0.95,0.25) 11(0.95,0.75) 12(0.95,1.25)
  rrect10% 1x2.65 smd paste-1000 mask+0: 13(0,0)
  silkscreen extent -1.87,-1.75 1.05,1.75, body extent -1.3,-1.65 1.3,1.65, height 0.25
ESD_Overlay_Small [mil]
  silkscreen extent -62,-48 64,61
FCC_disclaimer [mil]
Fiducial10-20 [mm]
  round 1 smd mask+0.5: 1(0,0)
  Top Layer keep-out circle w1.178: c0,0 r0.5
"FP-SFK-3045_FUSE, SMT-MFG" [mm]
  rrect7% 7.4x1.4 smd paste+0 mask+0: T1(0,2.05) T3(0,-2.05)
  round 1.729 smd paste+0 mask+0: T2(-4.942,0.045)
  Top Layer region: -3.8,-0.35 -3.8,0.35 -5.2,1.5 -5.95,1.5 -5.95,-1.5 -5.2,-1.5
  silkscreen extent -4.75,-2.5 4.75,3.42, body extent -6.05,-2.85 4.85,2.85, height 0.25
IEC_HotSurface_small [mil]
  silkscreen extent -107,-93 107,92
Label_650x200 [mil] "Thermal Transfer Label"
  round 1 on Mech13: 0(0,0)
  silkscreen extent -325,-100 325,100, body extent -325,-100 325,100, height 1
Mill-Max_800-10-008-10-001000 [mm] "Mill-Max"
  rect 1.5x1.5 hole 0.85: 1(-8.89,0)
  round 1.5 hole 0.85: 2(-6.35,0) 3(-3.81,0) 4(-1.27,0) 5(1.27,0) 6(3.81,0) 7(6.35,0) 8(8.89,0)
  silkscreen extent -10.16,-1.27 10.16,1.78, body extent -10.16,-1.27 10.16,1.27, height 8.13
Net-Tie_0805_HV_NoOverlay [mil] "0805_HV pads tied by 10mil copper trace which can be cut.  An 0805 part can be placed on pads."
  rect 50x63 smd paste-25: 1(-40,0) 2(40,0)
  Top Layer lines w10: -16,0 16,0
  Top Layer keep-out lines w1: -22,-30.91 -22,30.91 ; -14.96,-30.91 14.96,-30.91 ; -14.96,30.91 14.96,30.91 ; 22,-30.91 22,30.91
ONSC-SOD-123-2-425-04_V [mm] "SOD, 2-Leads, Body 2.69x1.6mm"
  rect 0.91x1.22 smd: 1(-1.635,0) 2(1.635,0)
  silkscreen extent -1.76,-0.8 0.78,1.28, body extent -1.35,-0.8 1.35,0.8, height 1.35
RDN0011A-MFG [mm]
  rrect42% 1.2x0.475 smd paste-1000 mask-1000: 1(-1.4,1.962) 8(1.4,1.962)
  rrect57% 1.2x0.35 smd paste-1000 mask-1000: 2(-1.4,1.15) 3(-1.4,0.65) 6(1.4,0.65) 7(1.4,1.15)
  rrect13% 1.6x2.15 smd paste-1000 mask-1000: 4(-1.2,-1) 5(1.2,-1)
  rrect57% 0.35x0.9 smd paste-1000 mask-1000: 9(0.5,2.05) 11(-0.5,2.05)
  round 0.504 smd paste-1000 mask-1000: 10(0,1.005)
  Top Layer region: -0.2,2.4 -0.187,2.45 -0.15,2.487 -0.1,2.5 -0.1,2.5 0.1,2.5 0.15,2.487 0.187,2.45 0.2,2.4 0.2,2.4 0.2,1.515 0.203,1.5 0.212,1.487 0.225,1.478 0.24,1.475 0.24,1.475 0.24,1.475 0.26,1.47 0.275,1.455 0.28,1.435 0.28,1.435 0.28,-1.975 0.267,-2.025 0.23,-2.062 0.18,-2.075 0.18,-2.075 -0.18,-2.075 -0.23,-2.062 -0.267,-2.025 -0.28,-1.975 -0.28,-1.975 -0.28,1.435 -0.275,1.455 -0.26,1.47 -0.24,1.475 -0.24,1.475 -0.24,1.475 -0.225,1.478 -0.212,1.487 -0.203,1.5 -0.2,1.515 -0.2,1.515
  silkscreen extent -2.67,-2.42 2.1,2.6, body extent -2.1,-2.4 2.1,2.6, height 0.25
RESC3216X60X45LL10T20 [mm] "Chip Resistor, 2-Leads, Body 3.20x1.60mm, IPC High Density"
  rect 0.9x1.6 smd: 1(-1.35,0) 2(1.35,0)
  silkscreen extent -0.5,-0.7 0.5,0.7, body extent -1.65,-0.85 1.65,0.85, height 0.6
RGR0020A-MFG [mm]
  rrect42% 0.6x0.24 smd paste+0 mask+0: 1(-1.65,1) 2(-1.65,0.5) 3(-1.65,0) 4(-1.65,-0.5) 5(-1.65,-1) 11(1.65,-1) 12(1.65,-0.5) 13(1.65,0) 14(1.65,0.5) 15(1.65,1)
  rrect42% 0.24x0.6 smd paste+0 mask+0: 6(-1,-1.65) 7(-0.5,-1.65) 8(0,-1.65) 9(0.5,-1.65) 10(1,-1.65) 16(1,1.65) 17(0.5,1.65) 18(0,1.65) 19(-0.5,1.65) 20(-1,1.65)
  rrect5% 2.05x2.05 smd paste-1000 mask+0: 21(0,0)
  silkscreen extent -2.65,-1.83 1.83,1.83, body extent -2.05,-2.05 2.05,2.05, height 0.25
Samtec_SSQ-110-03-x-D [mm] "Receptacle, 2.54mm, 10x2, TH"
  rect 1.55x1.55 hole 1.02: 1(-11.43,1.27)
  round 1.55 hole 1.02: 2(-11.43,-1.27) 3(-8.89,1.27) 4(-8.89,-1.27) 5(-6.35,1.27) 6(-6.35,-1.27) 7(-3.81,1.27) 8(-3.81,-1.27) 9(-1.27,1.27) 10(-1.27,-1.27) 11(1.27,1.27) 12(1.27,-1.27) 13(3.81,1.27) 14(3.81,-1.27) 15(6.35,1.27) 16(6.35,-1.27) 17(8.89,1.27) 18(8.89,-1.27) 19(11.43,1.27) 20(11.43,-1.27)
  silkscreen extent -12.95,-2.48 12.95,3, body extent -12.95,-2.48 12.95,2.48, height 8.51
SMA [mm] "Molded Diode, 2-Leads, Body 4.3x2.6mm, IPC Medium Density, based on OnSemi component dimensions and land pattern"
  rect 2x2 smd: 1(-2,0) 2(2,0)
  silkscreen extent -3.66,-1.57 2.79,1.57, body extent -2.6,-1.3 2.6,1.3, height 2.42
SMC_Bi [mil] "SMC, no polarity mark"
  rect 110x150 smd: 1(-140.49,0) 2(140.49,0)
  body extent -156,-116 156,116, height 92
SOD-123 [mm] "On Semi recommended land pattern"
  rect 0.915x1.22 smd: 1(-1.637,0) 2(1.637,0)
  silkscreen extent -2.74,-1.17 2.03,1.17, body extent -1.93,-0.9 1.93,0.9, height 1.35
SOD-323 [mm] "NXP recommended land pattern"
  rect 0.6x0.6 smd paste-0.05: 1(-1.1,0) 2(1.1,0)
  silkscreen extent -2.06,-0.86 1.53,0.86, body extent -1.3,-0.67 1.3,0.68, height 1.1
SOD-323F [mm] "NXP recommended land pattern"
  rect 0.6x0.6 smd paste-0.05: 1(-1.1,0) 2(1.1,0)
  silkscreen extent -2.06,-0.86 1.53,0.86, body extent -1.35,-0.67 1.35,0.68, height 0.79
SOT-23 [mm] "SOT23, 3-Leads, Body 2.9x1.3mm, Pitch 0.95mm, Lead Span 2.5mm, IPC Medium Density"
  rrect50% 1x0.6 smd: 1(-1.2,0.95) 2(-1.2,-0.95) 3(1.2,0)
  silkscreen extent -1.62,-1.5 0.7,1.5, body extent -1.16,-1.45 1.21,1.45, height 1
SW_RS-032G05A3-SM [mm] "SMT, 2-Leads, Body 6x3.5mm, Pin Spacing 8mm"
  rect 2x2 smd: 1(-4,0) 2(4,0)
  silkscreen extent -3,-1.75 3,1.75, body extent -4,-1.75 4,1.75, height 4.3
THERMISTOR_103AT-2 [mil] "SEMITEC"
  rect 65x65 hole 35: 1(-50,0)
  round 65 hole 35: 2(50,0)
  body extent -78,-47 79,47, height 338
TI_Stacked_Overlay_Small_Vertical [mil]
  silkscreen extent -66,-288 69,288
WL_SMCW_RED_1206 [mm] "SMD, 2-Leads, Body 3.2x1.6mm, Pitch 3mm"
  rect 1.4x1.5 smd: 1(-1.5,0) 2(1.5,0)
  silkscreen extent -2.9,-1.1 2.2,1.1, body extent -1.6,-0.85 1.6,0.85, height 0.78
WURTH_61300211121 [mm] "Header, 2.54mm, 2x1, TH"
  rrect50% 1.65x1.65 hole 1.15: 1(-1.27,0)
  round 1.65 hole 1.15: 2(1.27,0)
  body extent -2.54,-1.27 2.54,1.27, height 8.54

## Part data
C1 C6 C8 C9 C11 C12 C13 C18: library part CMP-0007445-2, "CAP, CERM, 0.22 uF, 50 V, +/- 10%, X7R, 0603", Cap_Case=0603, Manufacturer=MuRata, Supplier Part Number 1=490-12546-1-ND, TempCo=X7R, Tolerance_%=10%, Value1=Unknown, Value2=50V, ValueDisplayed=0.22uF
C2 C4 C5 C7 C10 C16 C17 C19 C23 C28 C29 C30 C31 C32 C33 C34 C35 C36 C37 C38 C39 C41: library part CMP-0007470-5, "CAP, CERM, 0.1 uF, 100 V, +/- 10%, X7R, 0603", Cap_Case=0603, Manufacturer=MuRata, Supplier Part Number 1=490-6439-1-ND, TempCo=X7R, Tolerance_%=10%, Value1=Unknown, Value2=100V, ValueDisplayed=0.1uF
C3 C27: library part CMP-0007455-4, "CAP, CERM, 470 pF, 50 V, +/- 10%, X7R, 0603", Cap_Case=0603, Manufacturer=MuRata, Supplier Part Number 1=490-1489-1-ND, TempCo=X7R, Tolerance_%=10%, Value1=Unknown, Value2=50V, ValueDisplayed=470pF
C14 C15: library part CMP-2006-02459-1, "1uF,25V", Manufacturer=Murata
C20: library part CMP-0009180-2, "CAP, CERM, 1 uF, 100 V, +/- 10%, X7R, 1210", Cap_Case=1210, Manufacturer=MuRata, Supplier Part Number 1=GRM32CR72A105KA35L-ND, TempCo=X7R, Tolerance_%=10%, Value1=Unknown, Value2=100V, ValueDisplayed=1uF
C21 C22: library part CMP-0075366-3, "CAP, CERM, 2.2 µF, 25 V,+/- 10%, X7S, 0603", Cap_Case=0603, Manufacturer=MuRata, Supplier Part Number 1=490-12732-1-ND, TempCo=X7S, Tolerance_%=10%, Value2=25V, ValueDisplayed=2.2µF
C24: library part CMP-0006619-1, "CAP, CERM, 1 uF, 35 V, +/- 10%, X5R, 0402", Cap_Case=0402, Manufacturer=MuRata, Supplier Part Number 1=490-10019-1-ND, TempCo=X5R, Tolerance_%=10%, Value1=Unknown, Value2=35V, ValueDisplayed=1uF
C25 C26: library part CMP-0008269-1, "CAP, CERM, 22 uF, 16 V, +/- 20%, X6S, 0805", Cap_Case=0805, Manufacturer=MuRata, Supplier Part Number 1=490-9956-1-ND, TempCo=X6S, Tolerance_%=20%, Value1=Unknown, Value2=16V, ValueDisplayed=22uF
D1 D2 D16: library part CMP-0028361-2, "Diode, Schottky, 60 V, 0.015 A, SOD-123", Manufacturer="Diodes Inc.", Value1=0.015A, Value2=0.8V
D3: library part CMP-0005787-1, "Diode, Zener, 5.6 V, 500 mW, SOD-123", Manufacturer="ON Semiconductor", Power_W=500mW, Supplier Part Number 1=MMSZ4690T1GOSCT-ND, Value1=0.5W
D4: library part CMP-1060-00574-1, "Zener Voltage Regulator  3.6v, 500 mW, 2-Pin SOD-123, Pb-Free, Tape and Reel", Manufacturer="On Semiconductor"
D5: library part CMP-0028447-2, "Diode, Schottky, 30 V, 0.2 A, SOD-323", Manufacturer="Diodes Inc.", Value1=0.2A, Value2=1V
D6: library part CMP-0005919-3, "Diode, TVS, Bi, 24 V, SOT-23", Manufacturer="ON Semiconductor", PartNumber=NUP2105LT1G, Value1=350W
D7: library part CMP-0028852-1, "Diode, Schottky, 10 V, 3 A, SOD-323F", Manufacturer=Nexperia, Supplier Part Number 1=568-4108-1-ND, Value1=3A, Value2=0.53V
D8: library part CMP-1060-00511-1, "Zener Voltage Regulator, 500 mW, 2-Pin SOD-123, Pb-Free, Tape and Reel", Manufacturer="On Semiconductor"
D9 D10 D11: library part CMP-0002935-1, "LED, Red, SMD", Color=Red, Manufacturer="Wurth Elektronik", Power_TotalModule=72mW, Supplier Part Number 1=732-4991-1-ND, Value1=0.072W, Value2=2V
D12 D14: library part CMP-0005692-3, "Diode, TVS, Bi, 30 V, 48.4 Vc, SMC", Manufacturer=Littelfuse, Value1=1500W
D13: library part CMP-0029196-2, "Diode, Ultrafast, 100 V, 2 A, SMA", Manufacturer="ON Semiconductor", Value1=2A, Value2=V
D15: library part CMP-0005754-3, "Diode, Zener, 16 V, 500 mW, SOD-123", Manufacturer="Diodes Inc.", Power_W=500mW, Value1=0.5W
F1: library part CMP-0086786-1, "Fuse, Self Control Protector, 45A, 6 to 7 cells, SMD", Manufacturer=Dexerials
FID1 FID2 FID3: library part CMP-0077181-1, "Fiducial mark.  There is nothing to buy or mount.", Manufacturer=N/A
J2 J3: library part CMP-0079854-1, "Receptacle, 2.54mm, 10x2, Tin, TH", Color=Black, Current_A=6.3A, Manufacturer=Samtec, Supplier Part Number 1=SAM1204-10-ND, Voltage_V=550V
J4 J5 J6 J7: library part CMP-0054794-2, "Header, 2.54 mm, 2x1, Gold, TH", Color=Black, Manufacturer="Wurth Elektronik", Supplier Part Number 1=732-5315-ND
J8: library part CMP-0055090-1, "Header, 100mil, 8x1, TH", Manufacturer=Mill-Max, Supplier Part Number 1=ED7208-ND
LBL1: library part CMP-0003625-1, "Thermal Transfer Printable Labels, 0.650\" W x 0.200\" H - 10,000 per roll", Manufacturer=Brady, Supplier Part Number 1=97C5133
Logo1: library part CMP-0074838-1, "Texas Instrument Corporate Signature"
Logo2: library part CMP-0074844-1
Logo3: library part IEC_HotSurface, "IEC 61010-1 Hot Surface Warning"
Logo4: library part CMP-0074840-1, "ESD Susceptible Symbol"
Logo5: library part CMP-0074847-1, "FCC_disclaimer"
NT1: library part CMP-0078142-5, "Single point connection between nets.", Manufacturer=N/A
Q1 Q2 Q3 Q4 Q5 Q6 Q7: library part CMP-0000433-1, "Transistor, NPN, 40 V, 0.8 A, SOT-23", Manufacturer="NXP Semiconductor", Supplier Part Number 1=568-6225-1-ND, Value1="0.8 A", Value2=300
Q8: library part CMP-0000848-1, "MOSFET, N-CH, 60 V, 1.2 A, SOT-23", Alternate Manufacturer=None, Manufacturer="International Rectifier", Supplier Part Number 1=IRLML2060TRPBFCT-ND, Value1=0.6, Value2="0.67 nC"
Q9 Q10 Q11 Q12: library part CMP-0000823-2, "MOSFET, N-CH, 60 V, 100 A, DNK0008A (VSON-CLIP-8)", Alternate Manufacturer=None, Manufacturer="Texas Instruments", Supplier Part Number 1=296-41076-1-ND, Value1=0.003, Value2="41 nC"
R1 R7 R11 R16 R20 R24 R28 R33: library part CMP-0021991-3, "RES, 100, 1%, 0.1 W, 0603", Manufacturer=Vishay-Dale, Power_W=100mW, Supplier Part Number 1=541-100HCT-ND, TempCo="100 ppm/C", Tolerance_%=1%, Value2=0.1W, Value_Code=100R, ValueDisplayed=100
R2 R3 R8 R9 R12 R13 R17: library part CMP-2003-02397-1, "RES, 80.6, 1%, 0.25 W, 1206", Manufacturer="Vishay Dale"
R4 R10 R14 R19 R23 R27 R31: library part CMP-0025781-1, "RES, 300, 5%, 0.1 W, 0603", Manufacturer=Vishay-Dale, Power_W=100mW, Supplier Part Number 1=541-300GCT-ND, TempCo="200 ppm/C", Tolerance_%=5%, Value2=0.1W, Value_Code=300R, ValueDisplayed=300
R5 R15 R22 R41 R43: library part CMP-0021998-4, "RES, 10.0 k, 1%, 0.1 W, AEC-Q200 Grade 0, 0603", Manufacturer=Vishay-Dale, Power_W=100mW, Supplier Part Number 1=541-10.0KHCT-ND, TempCo="100 ppm/C", Tolerance_%=1%, Value2=0.1W, Value_Code=10k0, ValueDisplayed=10.0k
R6 R30 R45: library part CMP-0025781-3, "RES, 300, 5%, 0.1 W, 0603", Manufacturer=Vishay-Dale, Power_W=100mW, Supplier Part Number 1=541-300GCT-ND, TempCo="200 ppm/C", Tolerance_%=5%, Value2=0.1W, Value_Code=300R, ValueDisplayed=300
R18 R34 R40 R44 R46 R47 R48 R49: library part CMP-0022109-5, "RES, 1.00 k, 1%, 0.1 W, AEC-Q200 Grade 0, 0603", Manufacturer=Vishay-Dale, Power_W=100mW, Supplier Part Number 1=541-1.00KHCT-ND, TempCo="100 ppm/C", Tolerance_%=1%, Value2=0.1W, Value_Code=1k00, ValueDisplayed=1.00k
R21: library part CMP-0026371-2, "RES, 41.2 k, 1%, 0.063 W, AEC-Q200 Grade 0, 0402", Manufacturer=Vishay-Dale, Power_W=63mW, Supplier Part Number 1=541-41.2KLCT-ND, TempCo="100 ppm/C", Tolerance_%=1%, Value2=0.063W, Value_Code=41k2, ValueDisplayed=41.2k
R25 R26 R29: library part CMP-0025813-4, "RES, 470, 5%, 0.1 W, AEC-Q200 Grade 0, 0603", Manufacturer=Vishay-Dale, Power_W=100mW, Supplier Part Number 1=541-470GCT-ND, TempCo="200 ppm/C", Tolerance_%=5%, Value2=0.1W, Value_Code=470R, ValueDisplayed=470
R32 R36 R37 R39 R42: library part CMP-0025700-4, "RES, 100, 5%, 0.1 W, AEC-Q200 Grade 0, 0603", Manufacturer=Vishay-Dale, Power_W=100mW, Supplier Part Number 1=541-100GCT-ND, TempCo="200 ppm/C", Tolerance_%=5%, Value2=0.1W, Value_Code=100R, ValueDisplayed=100
R35 R38: library part CMP-0022533-4, "RES, 60.4, 1%, 0.1 W, AEC-Q200 Grade 0, 0603", Manufacturer=Vishay-Dale, Power_W=100mW, Supplier Part Number 1=541-60.4HCT-ND, TempCo="100 ppm/C", Tolerance_%=1%, Value2=0.1W, Value_Code=60R4, ValueDisplayed=60.4
R54 R55: library part CMP-0021991-2, "RES, 100, 1%, 0.1 W, 0603", Manufacturer=Vishay-Dale, Power_W=100mW, Supplier Part Number 1=541-100HCT-ND, TempCo="100 ppm/C", Tolerance_%=1%, Value2=0.1W, Value_Code=100R, ValueDisplayed=100
R56 R58 R59 R60: library part CMP-0025785-3, "RES, 330, 5%, 0.1 W, 0603", Manufacturer=Vishay-Dale, Power_W=100mW, Supplier Part Number 1=541-330GCT-ND, TempCo="200 ppm/C", Tolerance_%=5%, Value2=0.1W, Value_Code=330R, ValueDisplayed=330
R57 R61: library part CMP-0025702-2, "RES, 10 M, 5%, 0.1 W, 0603", Manufacturer=Vishay-Dale, Power_W=100mW, Supplier Part Number 1=541-10MGCT-ND, TempCo="200 ppm/C", Tolerance_%=5%, Value2=0.1W, Value_Code=10M0, ValueDisplayed=10M
R62 R63: library part CMP-0015756-2, "RES, 0.002, 1%, 2 W, 2512", Manufacturer="Stackpole Electronics Inc", Power_W=2W, Supplier Part Number 1=CSNL2512FT2L00CT-ND, TempCo="50 ppm/C", Tolerance_%=1%, Value_Code=2L000, ValueDisplayed=0.002
RT1 RT3: library part CMP-0002341-2, "Thermistor NTC, 10.0k ohm, 1%, Disc, 5x8.4 mm", Manufacturer="SEMITEC Corporation", Power_W=10mW, Supplier Part Number 1=954-103AT-2, Tolerance_%=1%
RT2: library part CMP-0084566-1, "Thermistor, DEC0002A (X1SON-2)", Alternate Manufacturer="Texas Instruments", Alternate PartNumber=TMP6131DECT
S1: library part CMP-0002210-1, "Switch, Tactile, SPST-NO, 0.05A, 12V, SMD", CurrentRating_mA=50A, Manufacturer="C&K Components", Supplier Part Number 1=CKN10388CT-ND
U2: library part CMP-0092221-1, "Voltage and Temperature Protection for 3-Series to 7-Series Cell Li-Ion Batteries with Internal Delay Timer", Manufacturer="Texas Instruments", Max Supply Voltage=38.5V, Min Supply Voltage=5V, Nominal Supply Current=2uA, Operating Temperature Range="-65°C to +150°C"
U3: library part CMP-0091326-1, "2-s to 7-s High Accuracy Battery Monitor and Protector for Li-Ion, LiPolymer, and LiFePO4  Battery Packs", Manufacturer="Texas Instruments", Max Supply Voltage=38.5V, Min Supply Voltage=3V, Nominal Supply Current=120uA, Operating Temperature Range="-40°C to +110°C"
U4: library part CMP-0075992-1, "Automotive Fault Protected CAN Transceiver With Flexible Data-Rate, D0008A (SOIC-8)", Alternate Manufacturer="Texas Instruments", Alternate PartNumber=TCAN1042HGVDRQ1
U5: library part CMP-0098344-1, "3-V to 65-V Input, 1-V to 13-V Output, 600-mA Synchronous Buck Converter Power Module in a HotRod QFN Package", Manufacturer="Texas Instruments", Max Supply Voltage=65V, Min Supply Voltage=3.6V, Operating Temperature Range="-40°C to +125°C", Output Voltage=5V, Switching Frequency=1MHz
U6: library part CMP-0035592-1, "Single Output LDO, 150 mA, Fixed 3.3 V Output, 2.5 to 24 V Input, with Ultra-Low IQ, 5-pin SOT-23 (DBV), -40 to 125 degC, Green (RoHS & no Sb/Br)", Manufacturer="Texas Instruments"

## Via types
v1: diameter 24, hole 12, Top Layer to Bottom Layer, 526 vias
v2: diameter 20, hole 8, Top Layer to Bottom Layer, tented both sides, 55 vias
v3: diameter 19.68, hole 7.87, Top Layer to Bottom Layer, tented both sides, 8 vias
v4: diameter 19.68, hole 7.87, Top Layer to Bottom Layer, 8 vias
v5: diameter 15.75, hole 7.87, Top Layer to Bottom Layer, tented both sides, 2 vias
v6: diameter 13.78, hole 7.87, Top Layer to Bottom Layer, tented both sides, 2 vias
v7: diameter 24, hole 12, Top Layer to Bottom Layer, tented both sides, 1 vias

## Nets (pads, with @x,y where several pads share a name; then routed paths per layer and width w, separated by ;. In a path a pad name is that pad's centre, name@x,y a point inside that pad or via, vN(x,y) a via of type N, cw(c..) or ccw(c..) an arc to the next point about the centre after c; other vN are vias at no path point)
3.3V: C14.2 J4.1 R5.2 R15.2 R22.2 R41.1 U3.15 | length 1803.9
  Top Layer w10: R15.2@269.82,1294.05 R5.2@335.76,1294.05 ; R22.2@345.55,1621.86 345.55,1651.39 372,1677.84 372,1739.89 J4.1@381.01,1748.9 ; R5.2@349.86,1294.05 384.01,1294.05 v2(396.47,1306.51) ; C14.2@1195.71,1135.92 C14.2@1196.13,1135.5 C14.2@1199.08,1132.54 ; v2(1195.71,1174.72) 1241.19,1174.72 R41.1@1248.92,1167 ; 1199.08,1051.28 1208.81,1041.56 U3.15@1208.81,1012.22
  Top Layer w15: C14.2@1195.71,1135.92 v2(1195.71,1174.72) ; 1199.08,1051.28 C14.2@1199.08,1132.54
  Bottom Layer w10: v2@1191.18,1181.96 1191.18,1185.55 ; v2(1195.71,1174.72) v2@1195.71,1177.43
  Bottom Layer w15: J4.1@381.01,1748.9 372,1739.89 372,1330.98 v2(396.47,1306.51) 1070.22,1306.51 1191.18,1185.55 1194.75,1181.98 1194.75,1175.68 v2(1195.71,1174.72)
3V3_LDO: C17.2 C21.1 J6.1 U4.5 U6.3 | length 1542.3
  Top Layer w10: C21.1@832.75,1994.33 C21.1@829.38,1990.96 ; U6.3@851.38,1904.57 851.38,1945.95 829.38,1967.94 C21.1@829.38,1990.96 ; v1(900.55,1989.57) 832.75,1989.57 830.78,1989.57 C21.1@829.38,1990.96 ; U4.5@1247.54,1752.08 1252.57,1747.05 C17.2@1310.56,1747.05 ; C17.2@1308.14,1748.9 C17.2@1310.11,1746.93 ; v2(1310.88,1700.82) C17.2@1310.88,1743.87
  Top Layer w20: J6.1@385.26,1978.81 479.24,1978.81 542.27,2041.84 826.9,2041.84 832.75,2035.99 C21.1@832.75,1994.33
  Bottom Layer w10: v1(900.55,1989.57) 923.07,1967.05 923.07,1673.96 928.93,1668.1 1300.73,1668.1 1310.11,1677.48 v2@1310.11,1700.82
5V: C16.2 C22.1 C25.1 C26.1 D3.1 J7.2 U4.3 U5.4 U5.9 U6.2 | length 2252.7
  Top Layer w10: v2(509.75,1626.78) 510.95,1625.59 523.91,1625.59 536.43,1613.06 U5.9@576.18,1613.06 ; U5.4@680.12,1526.78 U5.4@680.12,1562.61 ; U5.4@712.4,1530.72 712.4,1546.08 U5.4@712.4,1562.61 ; C22.1@782.56,1752.08 782.56,1782.84 795.35,1795.63 795.35,1860.64 801.21,1866.5 U6.2@849.49,1866.5 ; C26.1@889.86,1546.08 C26.1@890.87,1545.07 942.43,1545.07 945.04,1542.45 v2(947.75,1542.45) ; C16.2@1197.54,1475.8 U4.3@1197.54,1545.39 ; D3.1@1199.45,1400.35 D3.1@1204.58,1395.22 ; v2@1204.58,1328.3 v2(1205.2,1327.68)
  Top Layer w20: J7.2@370.01,1863.91 550.67,1863.91 662.5,1752.08 C22.1@782.56,1752.08 782.56,1611.87 807.06,1587.37 C25.1@807.06,1546.08 ; U5.4@712.4,1546.08 C25.1@807.06,1546.08 ; C26.1@889.86,1546.08 C25.1@807.06,1546.08 ; D3.1@1199.45,1400.35 C16.2@1199.45,1474.25 ; v2@1204.58,1328.3 D3.1@1204.58,1395.22
  Bottom Layer w10: v2(509.75,1626.78) 509.75,1489.52 525.02,1474.25 685.53,1474.25 698.23,1486.95 v3@698.23,1525.21
  Bottom Layer w20: v2(947.75,1542.45) 947.75,1388.78 959.47,1377.07 1155.82,1377.07 v2(1205.2,1327.68)
  other v3: 678.48,1524.52 698.16,1524.52 717.85,1524.52 680.05,1561.92 712.34,1561.92
ALERT: J3.12 R41.2 U3.14 | length 798.5
  Top Layer w10: U3.14@1228.49,1012.22 1228.49,1054.59 1248.92,1075.02 1248.92,1102.54 R41.2@1251.25,1104.87 ; R41.2@1252.72,1108.77 v2(1294.67,1108.77) ; v2(1565.19,1204.9) 1566.91,1203.18 1813.64,1203.18 J3.12@1857.39,1159.43
  Bottom Layer w10: v2(1294.67,1108.77) 1435.45,1108.77 1468.36,1141.67 1468.36,1198.17 1475.08,1204.9 v2(1565.19,1204.9)
BAT+: C30.1 D14.2 F1.T1
  other v1: 3469.79,172.45 3591.73,172 3645.22,172 3537.68,173.06 3259,174.56 3309.67,174.56 3369.44,174.56 3424.58,174.56 3696.18,174.56 3749.67,174.56 3804.31,174.56 3857.8,174.56 3592.51,226 3646,226 3538.45,227.06 3370.22,228.56 3425.35,228.56 3469.79,228.56 3696.96,228.56 3750.45,228.56 3256.18,231.56 3309.67,231.56 3804.31,231.56 3857.8,231.56
BAT-: C35.2 D14.1 NT1.2 Q8.2 R54.1 R62.1 R63.1 | length 2702.3
  Top Layer w10: R54.1@1392.46,732.81 1392.46,663.28 1466,589.74 1466,412.88 1528.33,350.55 2328.87,350.55 2334.73,344.69 R62.1@2334.73,260.59 ; Q8.2@3824.6,580.24 v2(3824.6,627.01)
  Bottom Layer w10: 2847,249 2847,295.01 2852.86,300.87 3052.54,300.87 3082.24,330.57 3082.24,608.79 3100.47,627.01 v2(3824.6,627.01)
  other v1: 2717.04,78.22 2774.76,78.22 2717.04,127.03 2774.76,127.03 2374.33,174.56 2151.11,176.26 2202.97,176.05 2247.05,176.05 2307.4,176.05 2429.46,176.05 2488.65,176.05 2545.91,176.05 2601.76,176.26 2663.77,176.05 2718.91,176.26 2772.4,176.26 2375.97,211.66 2429.46,211.66 2488.65,211.66 2545.72,211.66 2601.76,211.66 2663.77,211.66 2247.05,213.93 2308.69,213.93 2202.97,215.42 2718.91,214.59 2772.4,214.59 2151.11,215.63 2150.98,250.48 2202.97,250.48
BUCK_EN: J2.9 R18.1 | length 590.8
  Top Layer w10: J2.9@69.18,1252 124.13,1306.95 124.13,1396.68 129.99,1402.54 465.89,1402.54 475.28,1411.93 R18.1@475.28,1477.85
CAN_RX: J3.19 R42.1 | length 1018.5
  Top Layer w10: R42.1@1360.91,1480.78 1360.91,1421.76 1447.64,1335.04 v1(1447.64,1262)
  Bottom Layer w10: v1(1447.64,1262) 1654.44,1262 1660.3,1256.14 1660.3,859.7 J3.19@1768,752
CAN_STB: J3.7 R39.1 | length 1096.3
  Top Layer w10: R39.1@968.55,1752.08 968.55,1751.72 968.23,1751.39 968.23,1683.79 1008.28,1643.74 1400.06,1643.74 1469.77,1574.03 1469.77,1423.11 1546.21,1346.67 J3.7@1768,1346.67
CAN_TX: J3.17 R37.1 | length 1304.9
  Top Layer w10: R37.1@1038.18,1485.38 1038.18,1328.3 1061.77,1304.71 v1(1393.31,1304.71)
  Bottom Layer w10: v1(1393.31,1304.71) 1692.11,1304.71 1697.96,1298.85 1697.96,922.04 J3.17@1768,852
CANH: D6.1 J5.2 R35.2 U4.7 | length 611.5
  Top Layer w10: J5.2@1099.58,2234.57 1107.07,2227.08 1107.07,2224.92 1099.58,2217.43 1099.58,2076.16 1105.44,2070.3 D6.1@1130.27,2070.3 1130.27,2013.21 1123.02,2005.96 1096.16,2005.96 1076.2,1985.99 R35.2@1076.2,1877.02 1076.2,1831.54 1094.17,1813.56 1141.68,1813.56 1147.54,1807.7 U4.7@1147.54,1752.08
CANL: D6.2 J5.1 R38.1 U4.6 | length 651.1
  Top Layer w10: U4.6@1197.54,1752.08 1197.54,1805.87 1205.23,1813.56 1259.35,1813.56 1268.01,1822.22 R38.1@1268.01,1877.02 1268.01,1989.57 1255.21,2002.36 1212.4,2002.36 1205.08,2009.69 D6.2@1205.08,2070.3 1234.2,2070.3 1240.06,2076.16 1240.06,2216.97 1238.12,2218.9 1238.12,2229.76 J5.1@1217.58,2250.31
"Cell 0": J8.1 Q7.2 R33.1 | length 585.1
  Top Layer w10: J8.1@1157.97,57.03 1275.37,57.03 1294.67,76.33 1294.67,299.15 1288.81,305.01 Q7.2@1239.08,305.01
  Top Layer w15: Q7.2@1239.08,305.01 R33.1@1239.08,464.57
"Cell 2": J8.3 Q5.2 R13.1 R24.1 R48.1 | length 1216.3
  Top Layer w10: Q5.2@963.08,305.01 963.08,297.62 969.82,290.88 970.9,290.88 1009.7,252.08 1009.7,153.93 1015.64,147.98 1015.64,144.39 ; R48.1@1025.83,715.29 1030.86,710.26 1030.86,662.26 v2(1052.5,640.62)
  Top Layer w15: Q5.2@963.08,305.01 R24.1@963.08,467.52
  Top Layer w30: J8.3@965.83,57.03 J8.3@957.97,57.03 963.53,62.59 963.53,95.87 1015.64,147.98 R13.1@1055.21,147.98
  Bottom Layer w10: J8.3@957.97,57.03 957.97,546.09 v2(1052.5,640.62)
"Cell 3": J8.4 Q4.2 R12.1 R20.1 R47.1 | length 1183.8
  Top Layer w10: Q4.2@824.92,305.01 824.92,298.78 831.66,292.04 841.2,292.04 863.17,270.07 863.17,155.53 869.03,149.67 899.94,149.67 909.94,139.67 R12.1@909.94,137.76 ; R47.1@887.25,709.77 887.25,647.7 v2(888.41,646.54)
  Top Layer w15: Q4.2@824.92,305.01 R20.1@824.92,467.75
  Top Layer w30: J8.4@857.97,57.03 912.97,112.03 912.97,148.42 915.68,151.13 R12.1@926.72,151.13
  Bottom Layer w10: J8.4@857.97,57.03 857.97,616.09 v2(888.41,646.54)
"Cell 4": J8.5 Q3.2 R9.1 R16.1 R46.1 | length 1166.9
  Top Layer w10: Q3.2@688.04,305.01 688.04,297.62 694.78,290.88 702.16,290.88 720.04,273 720.04,155.07 725.9,149.21 R9.1@789.6,149.21 ; J8.5@757.97,57.03 757.97,70.31 J8.5@770.69,83.03 ; v2(789.6,648.97) 789.6,691.8 795.8,698 795.8,700.44 R46.1@809.5,714.14
  Top Layer w15: Q3.2@688.04,305.01 R16.1@688.04,464.57
  Top Layer w30: J8.5@770.69,83.03 770.69,87.28 786.33,102.92 R9.1@786.33,134.66
  Bottom Layer w10: J8.5@757.97,57.03 757.97,617.34 v2(789.6,648.97)
"Cell 5": J8.6 Q2.2 R8.1 R11.1 R44.1 | length 1212.1
  Top Layer w10: Q2.2@549.25,305.01 549.25,297.62 555.99,290.88 563.38,290.88 588.86,265.4 588.86,153.16 594.72,147.3 R8.1@650.64,147.3 ; J8.6@634.36,57.03 J8.6@650.64,73.31 ; v2(747.13,651.34) R44.1@747.13,714.38
  Top Layer w15: Q2.2@549.25,305.01 R11.1@549.25,467.52
  Top Layer w30: R8.1@650.64,147.3 650.64,84.91 652.41,83.14 652.41,62.59 J8.6@657.97,57.03
  Bottom Layer w10: J8.6@657.97,57.03 657.97,565.97 743.34,651.34 v2(747.13,651.34)
"Cell 6": J8.7 Q1.2 R2.1 R7.1 R40.1 | length 1174.9
  Top Layer w10: Q1.2@410.57,305.01 410.57,297.21 442.06,265.71 442.06,154.82 447.92,148.96 514.02,148.96 R2.1@515.68,147.3 ; R40.1@621.79,711.18 621.79,649.1 v2@622.65,648.25
  Top Layer w15: Q1.2@410.57,305.01 R7.1@410.57,467.75
  Top Layer w30: R2.1@515.68,147.3 515.68,90.58 J8.7@537.78,68.48
  Bottom Layer w10: J8.7@557.97,57.03 557.97,569.19 622.57,633.8 622.57,649.26 v2@623.93,650.62
  other v2: 622.22,648.67
"Cell 7": C20.1 C23.1 D1.2 D2.2 D16.2 J8.8 R1.1 R3.1 R34.1 U5.3 | length 2963.2
  Top Layer w10: U5.3@631.3,1551.98 631.3,1537.51 631.3,1444.37 638.11,1437.56 638.11,1346.74 C20.1@642.78,1342.07 ; v2(640.06,1272.98) C20.1@640.06,1342.79 ; D16.2@913.7,1123.81 D16.2@913.61,1123.72 D16.2@914.12,1123.2
  Top Layer w20: D1.2@357.94,755.77 R34.1@430.02,755.77 ; D1.2@357.94,756.8 293.42,756.8 216.68,680.06 v1(216.68,589.57) 216.68,473.61 222.54,467.75 R1.1@268.31,467.75 268.31,159.02 280.03,147.3 R3.1@374.87,147.3 ; D2.2@864.46,1207.57 912.85,1159.19 D16.2@912.85,1113.24 ; D16.2@913.01,1112.37 D16.2@913.27,1112.63 ; v7(913.86,1084.76) D16.2@913.86,1122.94
  Top Layer w30: R3.1@374.87,147.3 374.87,85.87 392.26,68.48 J8.8@433.72,68.48
  Bottom Layer w20: v1(216.68,589.57) 216.68,692.13 462.73,938.18 882.26,938.18 913.49,969.4 913.49,1027.21 914,1027.72 ; v2(640.06,1272.98) 656.76,1256.27 896.54,1256.27 913.49,1239.33 913.49,1027.72
  other v6: 631.23,1524.52 631.23,1551.29
Cell_1: J8.2 Q6.2 R17.1 R28.1 R49.1 S1.2 | length 2374.1
  Top Layer w10: R49.1@706.24,1082.83 845.01,1082.83 850.87,1076.97 850.87,1028.03 1200.04,678.86 v2(1200.04,649.69) ; R28.1@1098.57,465.25 R28.1@1101.08,462.74 ; Q6.2@1101.08,305.01 1101.08,297.62 1107.82,290.88 1115.2,290.88 1148.92,257.16 1148.92,147.98 ; R17.1@1202.57,147.98 1260.83,147.98 v2(1261.51,147.3) ; v2(1615.55,163.58) 1615.55,216.82 S1.2@1619.55,220.82
  Top Layer w15: Q6.2@1101.08,305.01 R28.1@1101.08,462.74
  Top Layer w30: J8.2@1057.97,57.03 1148.92,147.98 R17.1@1202.57,147.98
  Bottom Layer w10: J8.2@1057.97,57.03 1057.97,507.53 v2@1200.08,649.64 ; v2(1261.51,147.3) 1599.27,147.3 v2(1615.55,163.58)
